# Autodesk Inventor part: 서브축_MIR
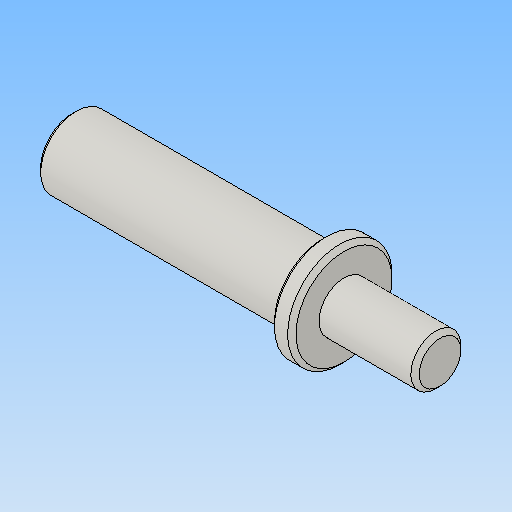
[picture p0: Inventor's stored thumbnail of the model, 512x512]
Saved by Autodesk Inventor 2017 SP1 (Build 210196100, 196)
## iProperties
Created: 2018-09
Part Number: 서브축_MIR
Material: 강철, 연강
Document SubType Name: Modeling
Designer: MRC
Density: 7.86 g/cm^3
Appearance: 강철
Mass: 142.801 g
Surface Area: 54.794 cm^2
Volume: 18.1681 cm^3
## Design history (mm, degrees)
derived "서브축.ipt"
  sketch "스케치1"
    geometry: L1 (18.818, -7)-(18.818, 7) reference; L2 (41.331, -13.5)-(41.331, 13.5) reference; L3 (46.5, 12.249)-(46.5, -12.249) reference; L4 (18.331, 0)-(106.5, 0) reference; L5 (18.331, 0)-(18.331, -6) reference; L6 (18.331, -6)-(41.331, -6) reference; L7 (41.331, -12.5)-(46.5, -12.5) reference; L8 (46.5, -8.5)-(106.5, -8.5) reference; L9 (106.5, -8.5)-(106.5, 0) reference; L10 (46.5, -8.5)-(46.5, -12.5) reference; L11 (41.331, -6)-(41.331, -12.5) reference; 2 further points
  sketch "스케치2"
    geometry: L1 (-11.5, 5)-(-11.5, -5) reference; L2 (5.5, -2)-(-4.5, -2) reference; L3 (-4.5, 2)-(5.5, 2) reference; A1 r 2 centre (-4.5, 0) between (-4.5, 2) and (-4.5, -2) reference; A2 r 2 centre (5.5, 0) between (5.5, -2) and (5.5, 2) reference; 2 further points
  sketch "스케치3"
    geometry: L1 (30, -7.5)-(30, 7.5) reference; L2 (30, 3)-(15, 3) reference; L3 (15, -3)-(30, -3) reference; A1 r 3 centre (15, 0) between (15, 3) and (15, -3) reference; 2 further points
  node "작업 평면1"
  node "작업 평면2"
feature "솔리드1::서브축.ipt"
tag "피쳐 태그1"
node "솔리드1"
